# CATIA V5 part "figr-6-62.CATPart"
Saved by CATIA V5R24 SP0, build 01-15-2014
Part number: Part1
Bounding box of the stored display mesh (mm): x -50.648 to 50.648, y -72.183 to 72.183, z -40 to 40
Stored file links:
  D:\KAVITA\CATIA V5-6R2014 Project_ Kavita\CATIA V5-6R2014_partfiles\Partfiles\c06_catia_v5-6r2014_prt\figr-6-62.CATPart
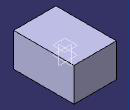
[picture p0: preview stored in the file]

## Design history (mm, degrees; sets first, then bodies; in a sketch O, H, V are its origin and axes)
Set1
  Plane1: type Offset, RefPlane xy-plane, Offset 20
Body1 (main body)
  Sketch1 on xy-plane, origin (0, 0, 0), H (1, 0, 0), V (0, 1, 0)
    line L1 (-50.6478, 72.1832) -> (50.6478, 72.1832)
    line L2 (50.6478, 72.1832) -> (50.6478, -72.1832)
    line L3 (50.6478, -72.1832) -> (-50.6478, -72.1832)
    line L4 (-50.6478, -72.1832) -> (-50.6478, 72.1832)
    axis line L5 (50.6478, -72.1832) -> (-50.6478, 72.1832)
    horizontal: L1 H, L3 H
    vertical: L2 V, L4 V
    midpoint: O L5
  Pad1: profile Sketch1, direction (0, 0, 1), length 40, mirrored extent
